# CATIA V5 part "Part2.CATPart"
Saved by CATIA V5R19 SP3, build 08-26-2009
Part number: Part2
Bounding box of the stored display mesh (mm): x -33.31 to 33.082, y -50.339 to 55.092, z 0 to 40
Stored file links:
  C:\Documents and Settings\mabart4\Desktop\Part2.CATPart
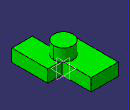
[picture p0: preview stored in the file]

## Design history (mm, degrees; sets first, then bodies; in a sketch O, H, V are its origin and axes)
Body1 (main body)
  Sketch1 on xy-plane, origin (0, 0, 0), H (1, 0, 0), V (0, 1, 0)
    line L1 (-33.3098, 55.0921) -> (10.4207, 55.0921)
    line L2 (0, -12.9834) -> (-33.3098, -12.9834)
    line L3 (-33.3098, -12.9834) -> (-33.3098, 55.0921)
    point P3 (0, -12.9834)
    point P5 (0, 7.7445)
    line L4 (10.4207, 7.7445) -> (33.0817, 7.7445)
    line L5 (33.0817, 7.7445) -> (33.0817, -50.3391)
    line L6 (33.0817, -50.3391) -> (0, -50.3391)
    line L7 (0, -50.3391) -> (0, -12.9834)
    line L8 (10.4207, 55.0921) -> (10.4207, 7.7445)
    horizontal: L1 H, L2 H, L4 H, L6 H
    vertical: L3 V, L5 V, L7 V, L8 V
    coincidence: P3 V, P3 L2, P5 L7, P5 L4
  Pad1: profile Sketch1, direction (0, 0, 1), length 20
  Sketch2 on end face of Pad1, origin (0, 0, 20), H (1, 0, 0), V (0, 1, 0)
    circle A1 centre (0, 0) radius 15.8892
  Pad2: profile Sketch2, direction (0, 0, 1), length 20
